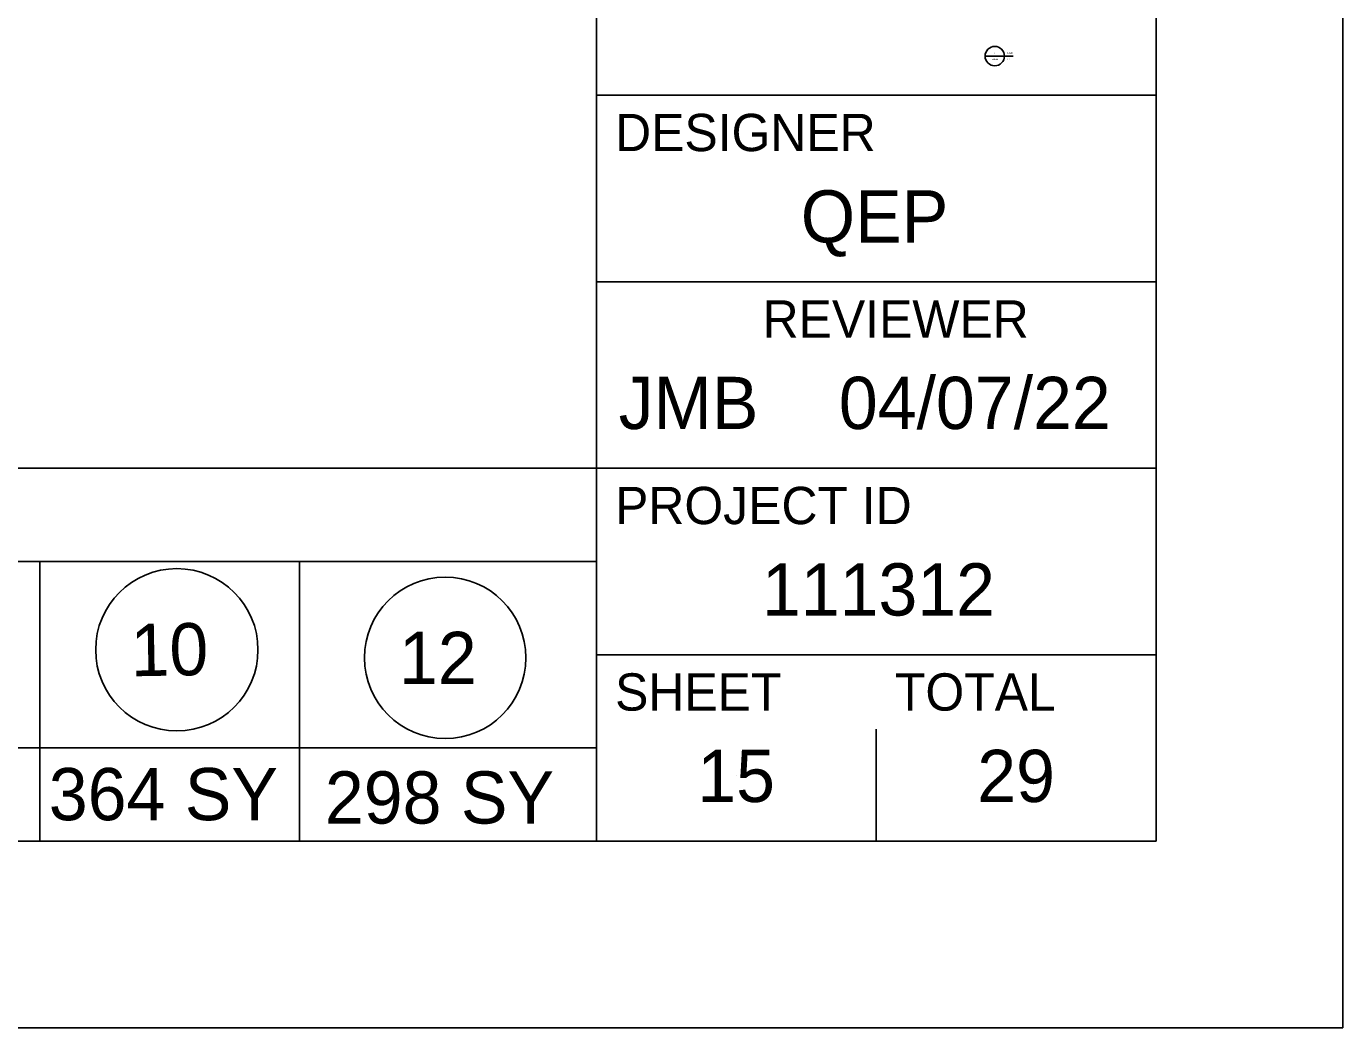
# Model space of a CAD drawing. Extents: x -34.1 to 34, y 0 to 22.
# Drawn here: x 30.472 to 34, y 0 to 2.685 of the extents above; entities that cross this region are included whole.
import ezdxf

# ---------------------------------------------------------------- set-up
doc = ezdxf.new("R2010")
doc.units = 0
for name, color, linetype in [('CS-ALGN-TEXT', 7, 'Continuous'), ('CS-ANNO', 7, 'Continuous'), ('CS-ANNO-MATC', 7, 'Continuous'), ('CS-ANNO-MATC-TEXT', 7, 'Continuous'), ('CS-ANNO-TABL', 7, 'Continuous')]:
    doc.layers.add(name, color=color, linetype=linetype)

msp = doc.modelspace()

# ---------------------------------------------------------------- linework, layer by layer
at = {"layer": 'CS-ALGN-TEXT'}
for p, q in [((26.2374, 1.5), (32, 1.5)), ((26.2374, 1.25), (32, 1.25)), ((30.5081, 0.5), (30.5081, 1.25)), ((31.204, 0.5), (31.204, 1.25)), ((32.75, 0.5), (32.75, 0.8)), ((26.2374, 0.75), (32, 0.75)), ((32.375, 0.675), (32.375, 0.675)), ((27.25, 0.5), (32, 0.5))]:
    msp.add_line(p, q, dxfattribs=at)
at = {"layer": 'CS-ANNO'}
msp.add_lwpolyline([(0, 0), (34, 0), (34, 22), (0, 22)], close=True, dxfattribs=at)
at = {"layer": 'CS-ANNO-MATC'}
for p, q in [((32, 0.5), (32, 21.5)), ((32, 2.5), (33.5, 2.5)), ((32, 2), (33.5, 2)), ((32, 1.5), (33.5, 1.5)), ((32, 1), (33.5, 1))]:
    msp.add_line(p, q, dxfattribs=at)
msp.add_lwpolyline([(1.5, 21.5), (33.5, 21.5), (33.5, 0.5), (1.5, 0.5)], close=True, dxfattribs=at)
at = {"layer": 'CS-ANNO-MATC-TEXT'}
for centre, radius in [((30.8754, 1.0132), 0.2175), ((31.5946, 0.9916), 0.2165)]:
    msp.add_circle(centre, radius, dxfattribs=at)
at = {"layer": 'CS-ANNO-TABL'}
for p, q in [((33.0415, 2.6047), (33.0936, 2.6047)), ((33.0678, 2.6047), (33.1173, 2.6047))]:
    msp.add_line(p, q, dxfattribs=at)
msp.add_circle((33.0676, 2.6047), 0.026, dxfattribs=at)

# ---------------------------------------------------------------- texts
at = {"layer": 'CS-ALGN-TEXT'}
for s, height, p in [('DESIGNER', 0.1, (32.05, 2.35)), ('QEP', 0.14, (32.5477, 2.105)), ('REVIEWER', 0.1, (32.4454, 1.85)), ('JMB', 0.14, (32.0596, 1.605)), ('04/07/22', 0.14, (32.6497, 1.605)), ('PROJECT ID', 0.1, (32.05, 1.35)), ('111312', 0.14, (32.4435, 1.105)), ('SHEET', 0.1, (32.05, 0.85)), ('TOTAL', 0.1, (32.8, 0.85)), ('15', 0.14, (32.2702, 0.605)), ('29', 0.14, (33.0206, 0.605))]:
    msp.add_text(s, height=height, dxfattribs=at).set_placement(p)
at = {"layer": 'CS-ANNO-MATC-TEXT'}
msp.add_text('10', height=0.14, rotation=1, dxfattribs=at).set_placement((30.7525, 0.9419))
for s, p in [('12', (31.4708, 0.9213)), ('364 SY', (30.5323, 0.5562)), ('298 SY', (31.2723, 0.5472))]:
    msp.add_text(s, height=0.14, dxfattribs=at).set_placement(p)
at = {"layer": 'CS-ANNO-TABL'}
for s, p in [('2', (33.0664, 2.6112)), ('Drawing', (33.1004, 2.6112)), ('5+00.00', (33.0596, 2.5948)), ('1:2', (33.1004, 2.5948))]:
    msp.add_text(s, height=0.00328, dxfattribs=at).set_placement(p)

doc.saveas('drawing.dxf')
